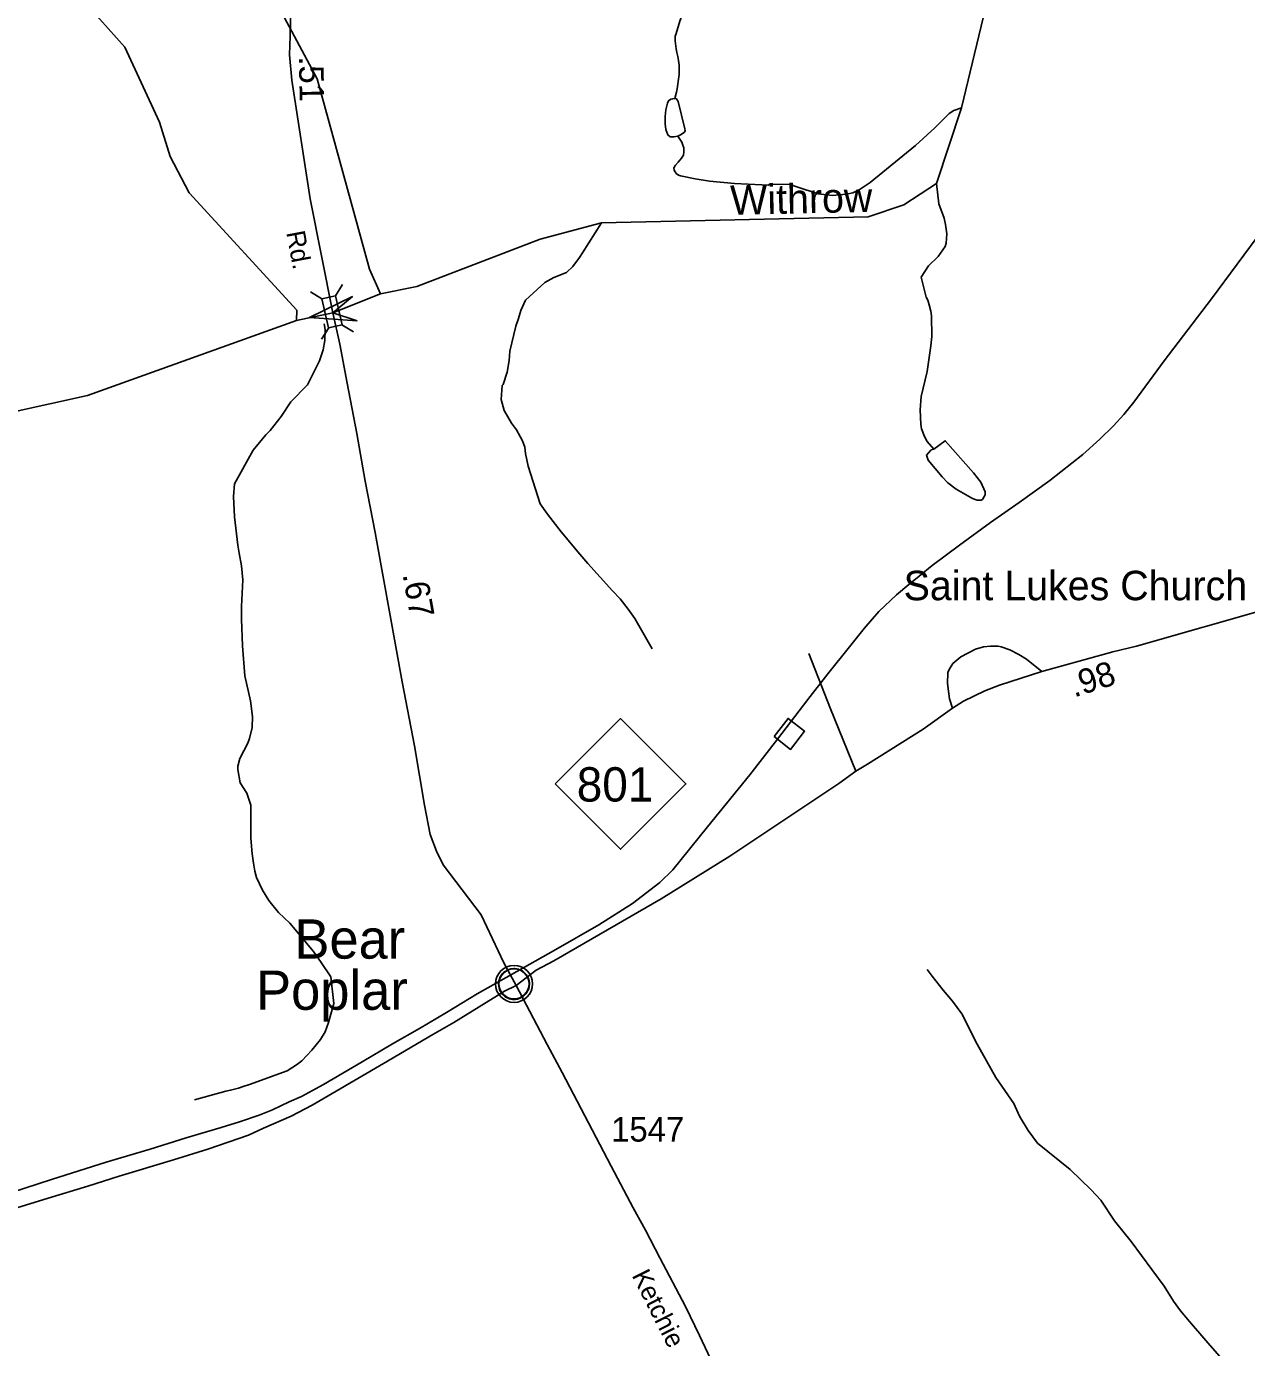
# Model space of a CAD drawing. Extents: x 1473865 to 1648260, y 639067 to 773536.
# Drawn here: x 1494517 to 1500735, y 703472 to 710204 of the extents above; entities that cross this region are included whole.
import ezdxf

# ---------------------------------------------------------------- set-up
doc = ezdxf.new("R2010")
doc.units = 0
for name, color, linetype in [('Exist Civil Demographics Community CELL', 7, 'Continuous'), ('Exist Civil Demographics Community Label', 7, 'Continuous'), ('Exist Cultural Church with Cemetery Label', 7, 'Continuous'), ('Exist Hydrographic Creek Single Shore', 7, 'Continuous'), ('Exist Hydrographic Creek Single Shore Label', 7, 'Continuous'), ('Exist Hydrographic Misc Water Feature', 7, 'Continuous'), ('Exist Railroad Mainline', 7, 'Continuous'), ('Exist Railroad Station CELL', 7, 'Continuous'), ('Exist Road Non-System Type 51', 7, 'Continuous'), ('Exist Road Primary NC Attributed', 7, 'Continuous'), ('Exist Road Primary NC Mileage Hundredths English Label', 7, 'Continuous'), ('Exist Road Primary NC Shield CELL', 7, 'Continuous'), ('Exist Road Primary NC Shield Number Label', 7, 'Continuous'), ('Exist Road Secondary Mileage Hundredths English Label', 7, 'Continuous'), ('Exist Road Secondary Structure Standard Bridge Attributed CELL', 7, 'Continuous'), ('Exist Road Secondary Structure Standard Bridge CELL', 7, 'Continuous'), ('Exist Road Secondary Type 51 Attributed', 7, 'Continuous'), ('Exist Road Secondary Type 51 Label', 7, 'Continuous'), ('Exist Road Secondary Type 51 Number Label', 7, 'Continuous')]:
    doc.layers.add(name, color=color, linetype=linetype)

msp = doc.modelspace()

# ---------------------------------------------------------------- linework, layer by layer
at = {"layer": 'Exist Civil Demographics Community CELL'}
msp.add_lwpolyline([(1496924.2, 705337.8), (1496925.2, 705343.4), (1496927, 705350), (1496929.9, 705357.2), (1496932.8, 705362.9), (1496936.2, 705368.7), (1496939.9, 705373.8), (1496943.9, 705378.2), (1496948.5, 705382.7), (1496954, 705387.3), (1496959.4, 705391), (1496964.3, 705393.9), (1496969.4, 705396.3), (1496974.8, 705398.6), (1496980.5, 705400.4), (1496984.8, 705401.6), (1496989.7, 705402.3), (1496993.8, 705403), (1497000.1, 705403.3), (1497004.6, 705403.2), (1497010.2, 705402.9), (1497015.2, 705402.2), (1497020.1, 705401.2), (1497025.1, 705399.8), (1497030.2, 705397.9), (1497036.9, 705395), (1497043.1, 705391.5), (1497048.2, 705387.9), (1497053.4, 705383.9), (1497056.7, 705380.8), (1497060.8, 705376.4), (1497064.7, 705371.7), (1497067.7, 705367.1), (1497070.9, 705362.1), (1497073.3, 705356.9), (1497075.4, 705351.9), (1497076.9, 705346.9), (1497078.2, 705342.3), (1497079.3, 705336.3), (1497079.9, 705331.6), (1497080.2, 705325.6), (1497080, 705319.8), (1497079.4, 705314.1), (1497078.5, 705308.6), (1497076.9, 705302.4), (1497075, 705296.6), (1497072.7, 705291.5), (1497069.5, 705285.5), (1497066.2, 705280.2), (1497062.8, 705275.5), (1497058.6, 705270.8), (1497053.3, 705265.8), (1497048.3, 705261.7), (1497043.2, 705258.2), (1497038.9, 705255.7), (1497032.1, 705252.5), (1497025, 705249.8), (1497019, 705248.3), (1497012.4, 705247), (1497008, 705246.6), (1497003.5, 705246.3), (1496997.9, 705246.3), (1496993.6, 705246.7), (1496988, 705247.4), (1496982.1, 705248.8), (1496977.5, 705250.1), (1496972.3, 705251.9), (1496967.7, 705253.9), (1496963.8, 705256.2), (1496957, 705260.2), (1496951.4, 705264.5), (1496946.5, 705269), (1496942, 705273.9), (1496938.9, 705277.8), (1496935.9, 705282), (1496931.8, 705289.1), (1496930.1, 705292.6), (1496928.4, 705296.7), (1496925.8, 705304.8), (1496924.2, 705311.9), (1496923.6, 705317.1), (1496923.2, 705323.4), (1496923.2, 705328.1), (1496923.7, 705334.5)], close=True, dxfattribs=at)
for centre, radius in [((1497001.8, 705325.4), 94.3), ((1497001.6, 705325.7), 76.7)]:
    msp.add_circle(centre, radius, dxfattribs=at)
at = {"layer": 'Exist Hydrographic Creek Single Shore'}
for points in [[(1496322.1, 708840.8), (1496506, 708879.8), (1497135, 709119.9), (1497448, 709203.2), (1498807.3, 709233.5), (1498989.1, 709295.9), (1499155.1, 709403.5), (1499282.9, 709789.9), (1499492.1, 710666.5), (1499486.7, 711012.3), (1499464.1, 711222.9), (1499627.1, 711479)], [(1495894, 708705.1), (1496079, 708744), (1496322.1, 708840.8)], [(1491375, 706698.7), (1491468, 706788.7), (1491691, 706934.6), (1491957.9, 707130.1), (1492715, 707525.1), (1493840.9, 708057.1), (1494444, 708238.7), (1494829, 708322.8), (1495894, 708705.1)]]:
    msp.add_lwpolyline(points, dxfattribs=at)
at = {"layer": 'Exist Hydrographic Misc Water Feature'}
for points in [[(1496322.1, 708840.8), (1496266, 708966.7), (1495999, 709937.2), (1495805, 710298.9), (1495569, 710677.9), (1495454, 711241.5), (1495490.1, 711907.2), (1495421.1, 712217.1), (1495396, 712234), (1495333, 712442.1), (1495127, 712620.2), (1494985, 713099.1), (1494989, 713289.4), (1495049, 713432.6), (1495028, 713607), (1494939, 713776.3), (1494934.4, 713901.5)], [(1495894, 708705.1), (1495895, 708757.6), (1495347, 709356.2), (1495250, 709542), (1495195, 709717.1), (1495018, 710098.1), (1494764, 710385.6), (1494512, 710771.4), (1494037, 711263.5), (1493857.9, 711533), (1493710, 711644.3), (1493596, 711814.1), (1493382.9, 712018.6), (1493252.9, 712201.8), (1493113, 712296.5), (1493021.9, 712341), (1492573, 712448.5), (1491982.9, 712526.1)], [(1497846.3, 710396), (1497867.6, 710325.8), (1497867.4, 710313.5), (1497865.6, 710294.7), (1497861.6, 710277.3), (1497856.9, 710257.1), (1497848.4, 710235.5), (1497825.8, 710162.6), (1497823.4, 710153.9), (1497822.9, 710130), (1497828.7, 710090.6), (1497832, 710071), (1497835.9, 710051.2), (1497839.9, 710030.8), (1497843.7, 710007.5), (1497843.9, 709979.9), (1497842.7, 709958.9), (1497839.1, 709924), (1497837.4, 709910.3), (1497833.9, 709885.7), (1497830, 709869), (1497821.9, 709837.5)], [(1497837.4, 709645), (1497816.4, 709641.5), (1497797.8, 709641.6), (1497785.5, 709651.3), (1497775.8, 709678.3), (1497771.8, 709708.2), (1497771.4, 709744.8), (1497775.1, 709780), (1497783.7, 709813.1), (1497788.8, 709825.4), (1497800.9, 709833.1), (1497810.6, 709835.9), (1497821.9, 709837.5)], [(1497821.9, 709837.5), (1497830.1, 709834.6), (1497838.4, 709821.3), (1497871.7, 709682), (1497874, 709672.5), (1497868.7, 709664.4), (1497849.8, 709652.4), (1497837.4, 709645)], [(1499282.9, 709789.9), (1499243.4, 709775.9), (1499219.1, 709760.4), (1499145.8, 709687.8), (1499048.2, 709597.8), (1498816.8, 709408.3), (1498760.1, 709371.4), (1498727.8, 709356), (1498695.7, 709348.6), (1498623.6, 709342), (1498551.7, 709351.3), (1498442.4, 709387.4), (1498408.6, 709398), (1498304.6, 709400), (1498296.5, 709396.1), (1498264.5, 709396.8), (1498124.6, 709403.4), (1497998.8, 709416), (1497924.9, 709427.2)], [(1497837.4, 709645), (1497847.3, 709630.5), (1497856.4, 709613.6), (1497862.7, 709599.8), (1497866.8, 709585.3), (1497867.3, 709565.9), (1497865.4, 709549), (1497855, 709532.8), (1497837.9, 709512.8), (1497824.6, 709497.7), (1497816, 709483.6), (1497818.3, 709472.2), (1497828.4, 709455.6), (1497839.5, 709446.7), (1497850.1, 709442.1), (1497924.9, 709427.2)], [(1499155.1, 709403.5), (1499166.9, 709299.7), (1499193.6, 709227.3), (1499201.1, 709195.1), (1499208.2, 709147.1), (1499203.3, 709099.2), (1499199, 709083.2), (1499163.7, 709031.3), (1499113.3, 708985), (1499076.2, 708925.7), (1499102.5, 708825.3), (1499110.1, 708809.1), (1499117.7, 708785), (1499125.1, 708752.9), (1499128.7, 708728.8), (1499130.9, 708624.8), (1499126, 708577), (1499107.7, 708445.4), (1499077.3, 708318.1), (1499072.1, 708250.3), (1499074.9, 708178.2), (1499078.5, 708154.2), (1499093.7, 708113.9), (1499107.3, 708089.7), (1499141.2, 708050)], [(1497448, 709203.2), (1497350.2, 709050.3), (1497335.7, 709026.6), (1497300.9, 708981.3), (1497268.4, 708949.9), (1497203.9, 708925.1), (1497158.5, 708898.9), (1497059.8, 708809.9), (1497036.9, 708756.4), (1497024.2, 708716.7), (1497011.4, 708677), (1496981.2, 708549.6), (1496976.3, 708501.8), (1496967.3, 708442), (1496947.3, 708380.4), (1496942, 708374.5), (1496936.7, 708302.6), (1496951.8, 708246.4), (1496988.6, 708181.8), (1497014, 708149.3), (1497045, 708092.7), (1497056.5, 708060.5), (1497059.8, 708028.5), (1497074.7, 707964.3), (1497135.3, 707771.3), (1497172.3, 707718.6), (1497242.7, 707629.3), (1497336.8, 707515.6), (1497377.9, 707466.9), (1497503.5, 707328.6), (1497542.7, 707287.8), (1497583.7, 707235.1), (1497617, 707186.5), (1497706.2, 707033)], [(1496034.3, 708688.3), (1496039, 708659.4), (1496038, 708603.5), (1496029.1, 708555.7), (1496010.1, 708500.1), (1495949.9, 708377.3), (1495864.4, 708291), (1495815, 708216), (1495759.7, 708145.1), (1495737.4, 708123.5), (1495671.9, 708044.8), (1495576.8, 707872.7), (1495571.7, 707808.8), (1495577.8, 707704.8), (1495595.2, 707560.6), (1495600.6, 707520.5), (1495613.4, 707456.3), (1495620.1, 707384.2), (1495613.7, 707248.4), (1495612.6, 707184.5), (1495618.1, 707048.5), (1495629.4, 706895.2), (1495658.4, 706767.9), (1495669.7, 706687.8), (1495666.7, 706631.8), (1495653.7, 706576.2), (1495645.3, 706552.3), (1495603.9, 706473.2), (1495595.1, 706435.3), (1495594.8, 706417.3), (1495605.6, 706349.2), (1495640.7, 706296.6), (1495661, 706236.2), (1495660.7, 706068.3), (1495667.2, 705988.3), (1495670.7, 705964.2), (1495674.3, 705940.2), (1495681.6, 705900.1), (1495689.1, 705868), (1495719.9, 705803.4), (1495752.4, 705749.6), (1495801.8, 705689.9), (1495858.9, 705634.9), (1495980.3, 705490.7), (1496019.3, 705434), (1496068.1, 705361.1), (1496083.2, 705225.8), (1496055.9, 705129.5), (1496039.1, 705081.9), (1496016.3, 705042.3), (1495971.3, 704987.2), (1495920.4, 704934.2), (1495894, 704912.7), (1495845.9, 704882.3), (1495654.2, 704813.3), (1495622, 704801.9), (1495597.8, 704794.4), (1495557.6, 704783.2), (1495533.5, 704779.6), (1495453.1, 704757.2), (1495372.8, 704734.7)], [(1499127.2, 708046.3), (1499141.2, 708050), (1499199.7, 708092.7), (1499343.1, 707930.3), (1499380.3, 707881.6), (1499403.4, 707833.2), (1499403.1, 707817.2), (1499388.7, 707793.5), (1499382.7, 707789.6), (1499362.7, 707790), (1499338.8, 707798.4), (1499291.2, 707825.3), (1499255.7, 707846), (1499212.2, 707878.7), (1499182.8, 707909.3), (1499112.2, 707994.6), (1499104.6, 708018.7), (1499127.2, 708046.3)], [(1500596.4, 703428.7), (1500527.7, 703508), (1500443.7, 703604.6), (1500398.4, 703660.3), (1500363.3, 703708.9), (1500314.6, 703785.8), (1500252.2, 703870.9), (1500146.7, 704012.8), (1500062.5, 704118.4), (1499992.4, 704223.6), (1499943.4, 704276.5), (1499835.2, 704380.5), (1499669.5, 704513.5), (1499622.7, 704578.3), (1499578, 704651.1), (1499549.2, 704715.6), (1499457.5, 704849.3), (1499362.5, 705018.9), (1499283.2, 705172.4), (1499236.4, 705237.2), (1499189.4, 705294.1), (1499132.6, 705365.1), (1499107.3, 705399.5)]]:
    msp.add_lwpolyline(points, dxfattribs=at)
at = {"layer": 'Exist Railroad Mainline'}
msp.add_lwpolyline([(1494441.1, 704261.7), (1494644, 704328.6), (1494923.1, 704416.6), (1495148, 704483.3), (1495330.8, 704540.7), (1495509.6, 704594.1), (1495603.2, 704621.8), (1495702.3, 704657.2), (1495770.7, 704684.3), (1495855.2, 704725.2), (1495919.6, 704752.1), (1496030.4, 704812.5), (1496228.1, 704927.8), (1496383.2, 705019.5), (1496520.2, 705097.4), (1496657.4, 705179.4), (1496814.8, 705275.1), (1497042.5, 705403.8), (1497215.7, 705501.3), (1497433.6, 705626.2), (1497605.1, 705735.6), (1497744.5, 705841.7), (1497811.8, 705907.3), (1497988.3, 706126.1), (1498204.2, 706390.9), (1498344.7, 706572.7), (1498499.5, 706774.5), (1498601.2, 706905.1), (1498711.2, 707043.4), (1498786.5, 707136.3), (1498861.7, 707223.2), (1498950.9, 707308.1), (1499013.6, 707361.1), (1499066, 707402.2), (1499133, 707457.3), (1499272.4, 707561.1), (1499430, 707677), (1499575.3, 707778.7), (1499732.8, 707890.6), (1499900.6, 708022.1), (1499987.8, 708100.8), (1500056.6, 708169.8), (1500109.4, 708227), (1500160.3, 708290.2), (1500315.2, 708500), (1500555.7, 708816.5), (1500949, 709346.7)], dxfattribs=at)
at = {"layer": 'Exist Railroad Station CELL'}
msp.add_lwpolyline([(1498327.1, 706585.2), (1498398, 706677.8), (1498482.5, 706613), (1498411.5, 706520.5)], close=True, dxfattribs=at)
at = {"layer": 'Exist Road Non-System Type 51'}
for points in [[(1498743, 706409.6), (1498614.8, 706726.2), (1498504.6, 707009.7)], [(1499692, 706917.9), (1499614.2, 706980.1), (1499574.5, 707004.6), (1499528.7, 707027.3), (1499484.6, 707042.6), (1499469.1, 707046.1), (1499429.1, 707046.7), (1499395, 707043.2), (1499352.9, 707031.8), (1499278.3, 706992.7), (1499237.8, 706957.3), (1499219.3, 706927.7), (1499213.2, 706911.8), (1499210.5, 706855.8), (1499221.3, 706777.6), (1499235.6, 706730.5)]]:
    msp.add_lwpolyline(points, dxfattribs=at)
at = {"layer": 'Exist Road Primary NC Attributed'}
for points in [[(1497013.6, 705317.4), (1497115.2, 705395.3), (1497205.2, 705443.3), (1497752.2, 705758.1), (1498101.2, 705976.9), (1498656.3, 706346.9), (1498743, 706409.6), (1498803.6, 706444.8), (1499086.1, 706622.6), (1499235.6, 706730.5), (1499291.9, 706765.7), (1499400.6, 706818.2), (1499475, 706847.1), (1499692, 706917.9), (1500053.4, 707016.7), (1500173.8, 707046.9), (1500865.1, 707242.9), (1501127.4, 707317.2), (1501251.7, 707349.3), (1501669.2, 707465.3)], [(1494424.3, 704171.4), (1494628.2, 704233.9), (1494829.4, 704294.3), (1494990.1, 704345.1), (1495267.1, 704429.6), (1495442.2, 704483.8), (1495545.6, 704518.2), (1495649.2, 704554.6), (1495724.8, 704589.6), (1495865.9, 704651.4), (1495973.7, 704707.7), (1496075.8, 704766.6), (1496336.9, 704919.2), (1496588.9, 705068.2), (1496694.7, 705128.6), (1496953.1, 705288.3), (1497013.6, 705317.4)]]:
    msp.add_lwpolyline(points, dxfattribs=at)
at = {"layer": 'Exist Road Primary NC Shield CELL'}
msp.add_lwpolyline([(1497212.2, 706344.3), (1497545.2, 706677.3), (1497878.2, 706344.3), (1497545.2, 706011.3)], close=True, dxfattribs=at)
at = {"layer": 'Exist Road Secondary Structure Standard Bridge Attributed CELL'}
msp.add_lwpolyline([(1496202.4, 708703.4), (1495959.2, 708721.1), (1496178.7, 708827.4), (1496079, 708744)], close=True, dxfattribs=at)
at = {"layer": 'Exist Road Secondary Structure Standard Bridge CELL'}
for p, q in [((1496128.3, 708889.7), (1496091.7, 708831.3)), ((1495964.4, 708852.2), (1496022.9, 708815.5)), ((1496057.9, 708668.5), (1496021.2, 708610.1)), ((1496125.1, 708683.9), (1496183.6, 708647.3))]:
    msp.add_line(p, q, dxfattribs=at)
msp.add_lwpolyline([(1496091.7, 708831.3), (1496125.4, 708684), (1496056.6, 708668.2), (1496022.9, 708815.5)], close=True, dxfattribs=at)
at = {"layer": 'Exist Road Secondary Type 51 Attributed'}
for points in [[(1496079, 708744), (1495963.4, 709325.2), (1495870.1, 709931), (1495858.5, 710059.4), (1495861.5, 710154.6), (1495864.8, 710306.3), (1495883.4, 710700.3), (1495918, 711144.9), (1495926, 711385.3)], [(1497012.7, 705317.1), (1496950.3, 705432.3), (1496833.9, 705677.3), (1496640.7, 705931.8), (1496607.5, 706001.3), (1496574.2, 706086), (1496545.2, 706236.3), (1496494.1, 706539), (1496431.6, 706864.1), (1496302.8, 707578.3), (1496294.2, 707626.3), (1496242.6, 707887), (1496200.7, 708129.6), (1496150.8, 708386.5), (1496113.6, 708584.6), (1496079, 708744)], [(1499147, 701817.6), (1499071.5, 701953.5), (1498996, 702095), (1498933.5, 702187), (1498890.2, 702246), (1498778.3, 702377), (1498618.6, 702561.2), (1498447, 702750), (1498361.8, 702849.6), (1498295.9, 702929.3), (1498181.3, 703070.9), (1498105.8, 703214.1), (1498032.1, 703354.2), (1497947.4, 703533), (1497875.7, 703681.1), (1497745.2, 703929), (1497671.4, 704069.8), (1497608.9, 704184.4), (1497496.3, 704396.6), (1497246.7, 704873.2), (1497171.2, 705016.7), (1497013.6, 705317.4)]]:
    msp.add_lwpolyline(points, dxfattribs=at)

# ---------------------------------------------------------------- texts
at = {"layer": 'Exist Civil Demographics Community Label'}
for s, p in [('Bear', (1495882.8, 705454.1)), ('Poplar', (1495687.4, 705193.4))]:
    msp.add_text(s, height=200, dxfattribs=at).set_placement(p)
at = {"layer": 'Exist Cultural Church with Cemetery Label'}
msp.add_text('Saint Lukes Church', height=150, dxfattribs=at).set_placement((1498987.2, 707280.4))
at = {"layer": 'Exist Hydrographic Creek Single Shore Label'}
msp.add_text('Withrow', height=150, rotation=1.29597, dxfattribs=at).set_placement((1498105.1, 709243.4))
at = {"layer": 'Exist Road Primary NC Mileage Hundredths English Label'}
msp.add_text('.98', height=125, rotation=17.74966, dxfattribs=at).set_placement((1499856.1, 706784.4))
at = {"layer": 'Exist Road Primary NC Shield Number Label'}
msp.add_text('801', height=175, dxfattribs=at).set_placement((1497321.4, 706254.5))
at = {"layer": 'Exist Road Secondary Mileage Hundredths English Label'}
for s, rotation, p in [('.51', 271.21806, (1495905.2, 710051)), ('.67', 280.22571, (1496433.4, 707411.5))]:
    msp.add_text(s, height=125, rotation=rotation, dxfattribs=at).set_placement(p)
at = {"layer": 'Exist Road Secondary Type 51 Label'}
for s, rotation, p in [('Rd.', 280.65773, (1495840.8, 709154.2)), ('Ketchie', 296.81406, (1497600.5, 703840.2))]:
    msp.add_text(s, height=95, rotation=rotation, dxfattribs=at).set_placement(p)
at = {"layer": 'Exist Road Secondary Type 51 Number Label'}
msp.add_text('1547', height=125, dxfattribs=at).set_placement((1497497, 704521.8))

doc.saveas('drawing.dxf')
